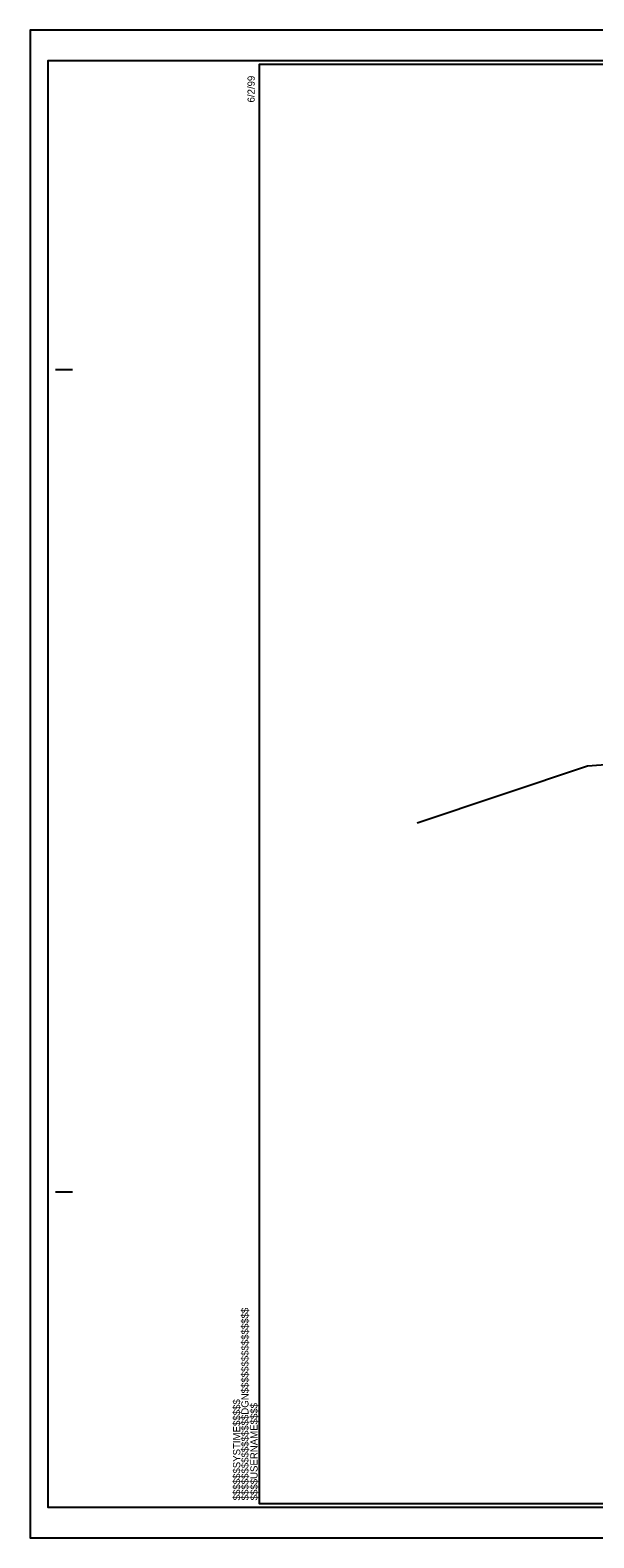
# Model space of a CAD drawing. Extents: x 2137858 to 2138172, y 2136084 to 2136289.
# Drawn here: x 2137858.1 to 2137934.9, y 2136083.7 to 2136289 of the extents above; entities that cross this region are included whole.
import ezdxf

# ---------------------------------------------------------------- set-up
doc = ezdxf.new("R2010")
doc.units = 0
for name, color, linetype in [('Old_Level_1', 7, 'Continuous'), ('Sheet Cutting Line CELL', 7, 'Continuous'), ('Sheet Plot Border Inside CELL', 7, 'Continuous'), ('Sheet Plot Border Outside CELL', 7, 'Continuous'), ('Sheet Typical CELL', 7, 'Continuous')]:
    doc.layers.add(name, color=color, linetype=linetype)

msp = doc.modelspace()

# ---------------------------------------------------------------- linework, layer by layer
at = {"layer": 'Old_Level_1'}
for p, q in [((2137942.17, 2136189.39), (2137934.06, 2136188.75)), ((2137934.06, 2136188.75), (2137910.84, 2136181.01))]:
    msp.add_line(p, q, dxfattribs=at)
at = {"layer": 'Sheet Cutting Line CELL'}
for p, q in [((2138172.48, 2136289.01), (2137858.14, 2136289.01)), ((2137858.14, 2136289.01), (2137858.14, 2136083.67)), ((2137858.14, 2136083.67), (2138172.48, 2136083.67))]:
    msp.add_line(p, q, dxfattribs=at)
at = {"layer": 'Sheet Plot Border Inside CELL'}
msp.add_lwpolyline([(2138171.64, 2136284.82), (2137860.56, 2136284.82), (2137860.56, 2136087.86), (2138171.64, 2136087.86)], close=True, dxfattribs=at)
at = {"layer": 'Sheet Plot Border Outside CELL'}
msp.add_lwpolyline([(2138172.48, 2136289.01), (2137858.14, 2136289.01), (2137858.14, 2136083.67), (2138172.48, 2136083.67)], close=True, dxfattribs=at)
at = {"layer": 'Sheet Typical CELL'}
for p, q in [((2137861.59, 2136242.81), (2137863.92, 2136242.81)), ((2137861.59, 2136130.81), (2137863.92, 2136130.81)), ((2137889.31, 2136088.34), (2137889.31, 2136088.34)), ((2137889.31, 2136088.34), (2137889.31, 2136088.34)), ((2137889.31, 2136088.34), (2137889.31, 2136088.34)), ((2137889.31, 2136088.34), (2137889.31, 2136088.34)), ((2137889.31, 2136088.34), (2137889.31, 2136088.34)), ((2137889.31, 2136088.34), (2137889.31, 2136088.34))]:
    msp.add_line(p, q, dxfattribs=at)
msp.add_lwpolyline([(2138169.31, 2136284.34), (2137889.31, 2136284.34), (2137889.31, 2136088.34), (2138169.31, 2136088.34)], close=True, dxfattribs=at)
msp.add_lwpolyline([(2137896.31, 2136088.34), (2137896.31, 2136088.34)], dxfattribs=at)

# ---------------------------------------------------------------- texts
for s, p in [('6/2/99', (2137888.72, 2136279.16)), ('$$$$$$$$$$$$$$$$DGN$$$$$$$$$$$$$$$$', (2137887.88, 2136088.78)), ('$$$$$$SYSTIME$$$$$', (2137886.75, 2136088.78)), ('$$$$USERNAME$$$$', (2137889.11, 2136088.78))]:
    msp.add_text(s, height=0.98, rotation=90, dxfattribs=at).set_placement(p)

doc.saveas('drawing.dxf')
